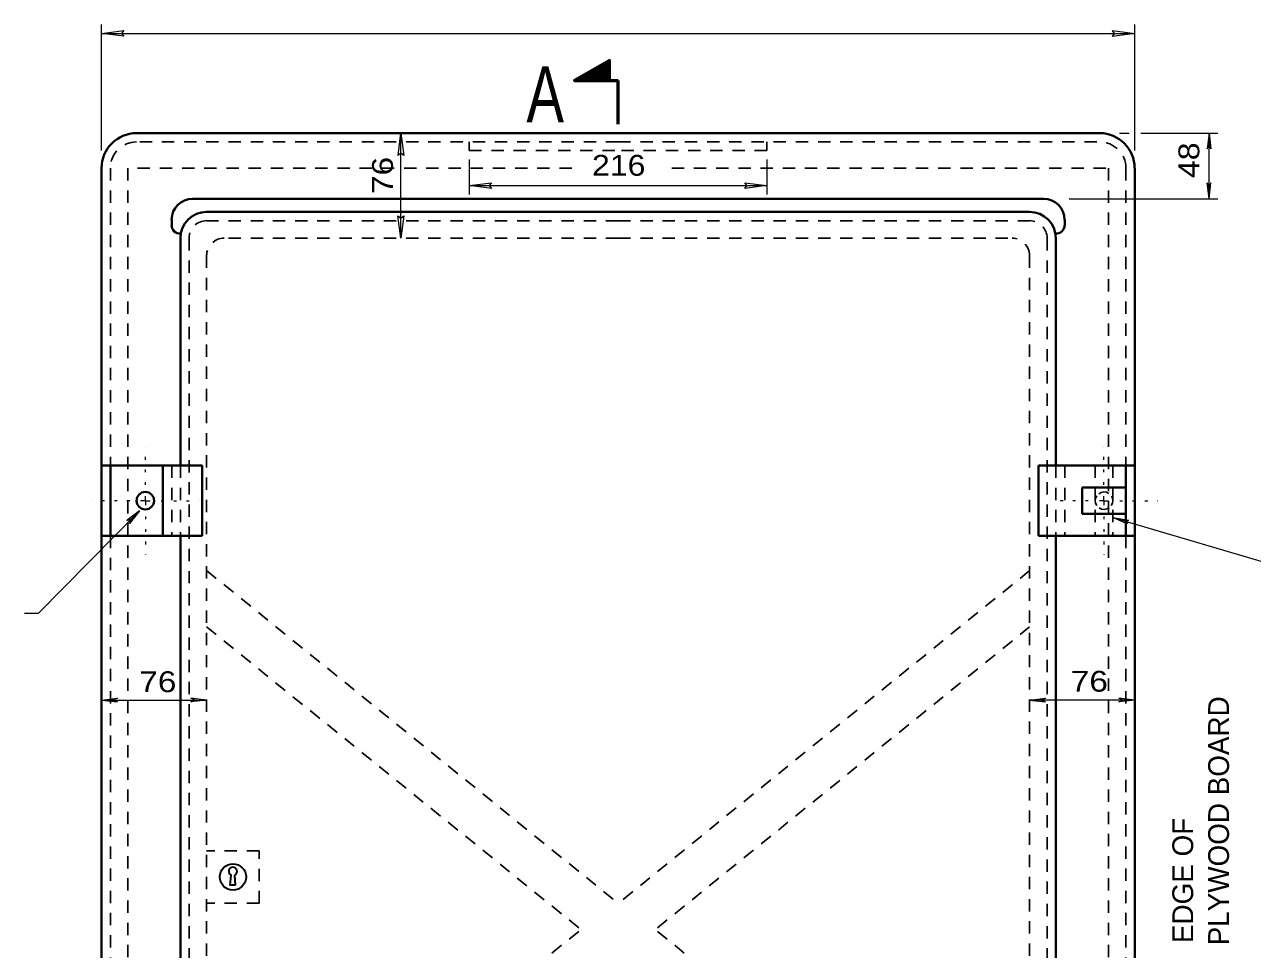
# Model space of a CAD drawing. Extents: x 312583 to 312854, y 144419 to 144597.
# Drawn here: x 312630.5 to 312675.3, y 144489.6 to 144523.37 of the extents above; entities that cross this region are included whole.
import ezdxf
from ezdxf.enums import TextEntityAlignment as Align

# ---------------------------------------------------------------- set-up
doc = ezdxf.new("R2010")
doc.units = 0
doc.header["$LTSCALE"] = 0.3
doc.linetypes.add('DOTTED', pattern=[1.5, 0.3, -1.2])
doc.linetypes.add('SHORT_DASHED', pattern=[2.7, 1.5, -1.2])
doc.layers.add('1', color=7, linetype='Continuous', lineweight=25)
doc.layers.add('2', color=7, linetype='Continuous', lineweight=13)

msp = doc.modelspace()

# ---------------------------------------------------------------- linework, layer by layer
at = {"layer": '1', "lineweight": 40}
for p, q in [((312652.1571, 144519.4027), (312634.5851, 144519.4027)), ((312652.1571, 144519.4027), (312669.7214, 144519.4027)), ((312633.3048, 144518.1223), (312633.3048, 144466.3723)), ((312671.0018, 144518.1223), (312671.0018, 144466.3723)), ((312652.1571, 144517.003), (312636.6321, 144517.003)), ((312652.1571, 144517.003), (312667.6821, 144517.003)), ((312635.8654, 144516.0447), (312635.8654, 144516.2363)), ((312652.1571, 144516.5277), (312637.1381, 144516.5277)), ((312652.1571, 144516.5277), (312667.1684, 144516.5277)), ((312668.4488, 144516.0447), (312668.4488, 144516.2363)), ((312636.1798, 144515.5693), (312636.1798, 144507.2663)), ((312668.1268, 144515.5693), (312668.1268, 144507.2663)), ((312636.9771, 144507.2663), (312633.3048, 144507.2663)), ((312633.6268, 144507.2663), (312633.6268, 144504.7057)), ((312635.5434, 144507.2663), (312635.5434, 144504.7057)), ((312636.9771, 144507.2663), (312636.9771, 144504.7057)), ((312667.4904, 144507.2663), (312671.0018, 144507.2663)), ((312667.4904, 144507.2663), (312667.4904, 144504.7057)), ((312670.6798, 144507.2663), (312670.6798, 144504.7057)), ((312669.0851, 144506.4613), (312669.0851, 144505.503)), ((312669.0851, 144506.4613), (312670.6798, 144506.4613)), ((312669.0851, 144505.503), (312670.6798, 144505.503)), ((312636.9771, 144504.7057), (312633.3048, 144504.7057)), ((312636.1798, 144504.7057), (312636.1798, 144483.6223)), ((312667.4904, 144504.7057), (312671.0018, 144504.7057)), ((312668.1268, 144504.7057), (312668.1268, 144483.6223))]:
    msp.add_line(p, q, dxfattribs=at)
at = {"layer": '1', "linetype": 'SHORT_DASHED'}
for p, q in [((312652.1571, 144519.0807), (312634.5851, 144519.0807)), ((312652.1571, 144519.0807), (312669.7214, 144519.0807)), ((312633.6268, 144518.1223), (312633.6268, 144507.2663)), ((312634.2631, 144518.1223), (312634.2631, 144466.3723)), ((312650.4628, 144518.1223), (312634.2631, 144518.1223)), ((312654.1121, 144518.1223), (312670.0434, 144518.1223)), ((312670.0434, 144518.1223), (312670.0434, 144466.3723)), ((312670.6798, 144518.1223), (312670.6798, 144507.2663)), ((312652.1571, 144516.2057), (312637.1381, 144516.2057)), ((312652.1571, 144516.2057), (312667.1684, 144516.2057)), ((312636.5018, 144515.5693), (312636.5018, 144469.7303)), ((312652.1571, 144515.5693), (312637.7821, 144515.5693)), ((312652.1571, 144515.5693), (312666.5321, 144515.5693)), ((312667.8048, 144515.5693), (312667.8048, 144469.7303)), ((312637.1381, 144514.933), (312637.1381, 144470.3667)), ((312667.1684, 144514.933), (312667.1684, 144470.3667)), ((312635.8654, 144507.2663), (312635.8654, 144504.7057)), ((312636.1798, 144507.2663), (312636.1798, 144504.7057)), ((312668.1268, 144507.2663), (312668.1268, 144504.7057)), ((312668.4488, 144507.2663), (312668.4488, 144504.7057)), ((312669.5604, 144507.2663), (312669.5604, 144504.7057)), ((312670.2044, 144507.2663), (312670.2044, 144504.7057)), ((312633.6268, 144504.7057), (312633.6268, 144483.6223)), ((312670.6798, 144504.7057), (312670.6798, 144483.6223)), ((312637.1381, 144503.433), (312652.1571, 144491.289)), ((312667.1684, 144503.433), (312652.1571, 144491.289)), ((312637.1381, 144501.3783), (312650.8001, 144490.3307)), ((312667.1684, 144501.3783), (312653.5064, 144490.3307)), ((312639.0548, 144493.2057), (312637.1381, 144493.2057)), ((312639.0548, 144491.289), (312639.0548, 144493.2057)), ((312639.0548, 144491.289), (312637.1381, 144491.289)), ((312637.1381, 144479.2907), (312650.8001, 144490.3307)), ((312667.1684, 144479.2907), (312653.5064, 144490.3307))]:
    msp.add_line(p, q, dxfattribs=at)
at = {"layer": '1', "linetype": 'DOTTED', "lineweight": 13}
for p, q in [((312634.9071, 144506.561), (312634.9071, 144507.941)), ((312669.8824, 144506.561), (312669.8824, 144507.941)), ((312634.3321, 144505.986), (312632.9444, 144505.986)), ((312635.4821, 144505.986), (312636.8621, 144505.986)), ((312669.3074, 144505.986), (312667.9274, 144505.986)), ((312670.4574, 144505.986), (312671.8451, 144505.986)), ((312634.9071, 144505.411), (312634.9071, 144504.0233)), ((312669.8824, 144505.411), (312669.8824, 144504.0233))]:
    msp.add_line(p, q, dxfattribs=at)
at = {"layer": '1', "lineweight": 13}
for p, q in [((312634.9071, 144505.986), (312634.7308, 144505.986)), ((312634.9071, 144505.986), (312634.9071, 144506.1547)), ((312634.9071, 144505.986), (312635.0758, 144505.986)), ((312634.9071, 144505.986), (312634.9071, 144505.8173)), ((312669.8824, 144505.986), (312669.7138, 144505.986)), ((312669.8824, 144505.986), (312669.8824, 144506.1547)), ((312669.8824, 144505.986), (312670.0511, 144505.986)), ((312669.8824, 144505.986), (312669.8824, 144505.8173))]:
    msp.add_line(p, q, dxfattribs=at)
at = {"layer": '1', "lineweight": 35}
msp.add_line((312638.1961, 144491.9483), (312638.1654, 144492.3163), dxfattribs=at)
at = {"layer": '1', "linetype": 'SHORT_DASHED'}
for points in [[(312646.7214, 144519.0807), (312646.7214, 144518.7663), (312652.1571, 144518.7663)], [(312657.5851, 144519.0807), (312657.5851, 144518.7663), (312652.1571, 144518.7663)]]:
    msp.add_lwpolyline(points, dxfattribs=at)
at = {"layer": '1', "lineweight": 35}
msp.add_lwpolyline([(312638.1961, 144491.9483), (312637.9968, 144491.9483), (312638.0351, 144492.3163)], dxfattribs=at)
at = {"layer": '1', "lineweight": 40}
msp.add_circle((312634.9033, 144505.986), 0.3194, dxfattribs=at)
at = {"layer": '1', "lineweight": 35}
msp.add_circle((312638.0977, 144492.2499), 0.4792, dxfattribs=at)
at = {"layer": '1', "lineweight": 40}
for centre, radius, start, end in [((312634.5838, 144518.1249), 1.2778, 90, 180), ((312669.7227, 144518.1249), 1.2778, 0, 90), ((312636.6283, 144516.2402), 0.7667, 90, 180), ((312667.6783, 144516.2402), 0.7667, 0, 90), ((312637.1394, 144515.5693), 0.9583, 90, 180), ((312667.1672, 144515.5693), 0.9583, 0, 90), ((312636.181, 144516.0485), 0.3194, 180, 272.41345), ((312668.1255, 144516.0485), 0.3194, 267.58655, 0)]:
    msp.add_arc(centre, radius, start, end, dxfattribs=at)
at = {"layer": '1', "linetype": 'SHORT_DASHED'}
for centre, radius, start, end in [((312634.5838, 144518.1249), 0.9583, 90, 180), ((312669.7227, 144518.1249), 0.9583, 0, 90), ((312637.1394, 144515.5693), 0.6389, 90, 180), ((312667.1672, 144515.5693), 0.6389, 0, 90), ((312637.7783, 144514.9304), 0.6389, 90, 180), ((312666.5283, 144514.9304), 0.6389, 0, 90)]:
    msp.add_arc(centre, radius, start, end, dxfattribs=at)
at = {"layer": '1'}
for start, end in [(56.61149, 126.70759), (145.14079, 213.35403), (326.83677, 32.29727), (236.53462, 306.15074)]:
    msp.add_arc((312669.8824, 144505.986), 0.3194, start, end, dxfattribs=at)
at = {"layer": '1', "lineweight": 35}
msp.add_arc((312638.0964, 144492.4556), 0.1521, 295.8624, 245.15761, dxfattribs=at)
at = {"layer": '2'}
for p, q in [((312633.3048, 144518.7663), (312633.3048, 144523.3663)), ((312671.0018, 144518.7663), (312671.0018, 144523.3663)), ((312633.3048, 144523.0443), (312671.0018, 144523.0443)), ((312644.2298, 144515.5693), (312644.2298, 144519.4027)), ((312670.4421, 144519.4027), (312670.8024, 144519.4027)), ((312671.2241, 144519.4027), (312674.0378, 144519.4027)), ((312673.7158, 144519.4027), (312673.6468, 144518.8277)), ((312673.7158, 144517.003), (312673.7158, 144519.4027)), ((312673.7158, 144519.4027), (312673.7848, 144518.8277)), ((312673.6468, 144518.8277), (312673.7158, 144519.0117)), ((312673.7848, 144518.8277), (312673.7158, 144519.0117)), ((312646.7214, 144518.4443), (312646.7214, 144517.164)), ((312657.5851, 144518.4443), (312657.5851, 144517.164)), ((312646.7214, 144517.486), (312657.5851, 144517.486)), ((312673.6468, 144517.5857), (312673.7158, 144517.4017)), ((312673.7158, 144517.003), (312673.6468, 144517.5857)), ((312673.7848, 144517.5857), (312673.7158, 144517.4017)), ((312673.7158, 144517.003), (312673.7848, 144517.5857)), ((312668.6174, 144517.003), (312674.0378, 144517.003)), ((312631.0048, 144501.8767), (312634.6848, 144505.618)), ((312634.6848, 144505.618), (312634.2248, 144505.2577)), ((312634.6848, 144505.618), (312634.3244, 144505.158)), ((312634.2248, 144505.2577), (312634.4088, 144505.3343)), ((312634.3244, 144505.158), (312634.4088, 144505.3343)), ((312630.4957, 144501.8767), (312631.0048, 144501.8767)), ((312633.3048, 144498.7103), (312633.8874, 144498.7793)), ((312633.3048, 144498.7103), (312637.1381, 144498.7103)), ((312633.3048, 144498.7103), (312633.8874, 144498.6413)), ((312633.8874, 144498.7793), (312633.7034, 144498.7103)), ((312633.8874, 144498.6413), (312633.7034, 144498.7103)), ((312636.5631, 144498.7793), (312636.7471, 144498.7103)), ((312637.1381, 144498.7103), (312636.5631, 144498.7793)), ((312636.5631, 144498.6413), (312636.7471, 144498.7103)), ((312637.1381, 144498.7103), (312636.5631, 144498.6413)), ((312667.1684, 144498.7103), (312667.7434, 144498.7793)), ((312671.0018, 144498.7103), (312667.1684, 144498.7103)), ((312667.1684, 144498.7103), (312667.7434, 144498.6413)), ((312667.7434, 144498.7793), (312667.5594, 144498.7103)), ((312667.7434, 144498.6413), (312667.5594, 144498.7103)), ((312670.4268, 144498.7793), (312670.6108, 144498.7103)), ((312671.0018, 144498.7103), (312670.4268, 144498.7793)), ((312670.4268, 144498.6413), (312670.6108, 144498.7103)), ((312671.0018, 144498.7103), (312670.4268, 144498.6413))]:
    msp.add_line(p, q, dxfattribs=at)
at = {"layer": '2', "lineweight": 35}
for p, q in [((312651.8351, 144521.6183), (312651.6511, 144521.948)), ((312651.8351, 144521.6567), (312651.6588, 144521.9557)), ((312651.8351, 144521.6873), (312651.6741, 144521.9633)), ((312651.8351, 144521.718), (312651.6894, 144521.971)), ((312651.8351, 144521.7487), (312651.6971, 144521.9787)), ((312651.8351, 144521.7793), (312651.7201, 144521.9863)), ((312651.8351, 144521.81), (312651.7278, 144521.994)), ((312651.8351, 144521.8407), (312651.7431, 144522.0017)), ((312651.8351, 144521.879), (312651.7584, 144522.0093)), ((312651.8351, 144521.902), (312651.7738, 144522.017)), ((312651.8351, 144521.9403), (312651.7891, 144522.0247)), ((312651.8351, 144521.971), (312651.8044, 144522.0323)), ((312651.8351, 144522.0093), (312651.8121, 144522.04)), ((312651.8351, 144522.04), (312651.8274, 144522.0477)), ((312650.9764, 144521.3193), (312650.8768, 144521.5033)), ((312650.9918, 144521.3193), (312650.8844, 144521.5033)), ((312651.0148, 144521.3193), (312650.8998, 144521.5187)), ((312651.0378, 144521.3193), (312650.9151, 144521.5187)), ((312651.0531, 144521.3193), (312650.9304, 144521.534)), ((312651.0684, 144521.3193), (312650.9458, 144521.534)), ((312651.0838, 144521.3193), (312650.9611, 144521.5493)), ((312651.1068, 144521.3193), (312650.9688, 144521.557)), ((312651.1221, 144521.3193), (312650.9841, 144521.5647)), ((312651.1451, 144521.3193), (312650.9994, 144521.5723)), ((312651.1604, 144521.3193), (312651.0071, 144521.58)), ((312651.1834, 144521.3193), (312651.0224, 144521.5877)), ((312651.1988, 144521.3193), (312651.0378, 144521.5953)), ((312651.2141, 144521.3193), (312651.0531, 144521.603)), ((312651.2371, 144521.3193), (312651.0684, 144521.6107)), ((312651.2524, 144521.3193), (312651.0838, 144521.6183)), ((312651.2678, 144521.3193), (312651.0991, 144521.626)), ((312651.2908, 144521.3193), (312651.1068, 144521.6337)), ((312651.3138, 144521.3193), (312651.1221, 144521.6413)), ((312651.3291, 144521.3193), (312651.1374, 144521.649)), ((312651.3444, 144521.3193), (312651.1451, 144521.6567)), ((312651.3674, 144521.3193), (312651.1604, 144521.6643)), ((312651.3828, 144521.3193), (312651.1758, 144521.672)), ((312651.4058, 144521.3193), (312651.1911, 144521.6873)), ((312651.4211, 144521.3193), (312651.2064, 144521.6873)), ((312651.4364, 144521.3193), (312651.2218, 144521.7027)), ((312651.4518, 144521.3193), (312651.2371, 144521.7027)), ((312651.4748, 144521.3193), (312651.2524, 144521.718)), ((312651.4978, 144521.3193), (312651.2601, 144521.718)), ((312651.5131, 144521.3193), (312651.2754, 144521.7333)), ((312651.5284, 144521.3193), (312651.2908, 144521.7333)), ((312651.5438, 144521.3193), (312651.2984, 144521.7487)), ((312651.5668, 144521.3193), (312651.3138, 144521.7487)), ((312651.5898, 144521.3193), (312651.3291, 144521.764)), ((312651.6051, 144521.3193), (312651.3444, 144521.764)), ((312651.6204, 144521.3193), (312651.3598, 144521.7793)), ((312651.6434, 144521.3193), (312651.3751, 144521.787)), ((312651.6588, 144521.3193), (312651.3904, 144521.7947)), ((312651.6818, 144521.3193), (312651.3981, 144521.8023)), ((312651.6971, 144521.3193), (312651.4134, 144521.81)), ((312651.7124, 144521.3193), (312651.4288, 144521.8177)), ((312651.7354, 144521.3193), (312651.4364, 144521.8253)), ((312651.7508, 144521.3193), (312651.4518, 144521.833)), ((312651.7738, 144521.3193), (312651.4671, 144521.8407)), ((312651.7891, 144521.3193), (312651.4824, 144521.8483)), ((312651.8044, 144521.3193), (312651.4978, 144521.856)), ((312651.8274, 144521.3193), (312651.5131, 144521.8637)), ((312651.8351, 144521.3347), (312651.5208, 144521.8713)), ((312651.8351, 144521.3653), (312651.5438, 144521.879)), ((312651.8351, 144521.396), (312651.5514, 144521.8867)), ((312651.8351, 144521.4267), (312651.5668, 144521.8943)), ((312651.8351, 144521.4573), (312651.5821, 144521.902)), ((312651.8351, 144521.488), (312651.5898, 144521.9173)), ((312651.8351, 144521.5187), (312651.6051, 144521.9173)), ((312651.8351, 144521.557), (312651.6204, 144521.9327)), ((312651.8351, 144521.5877), (312651.6358, 144521.9403)), ((312650.5701, 144521.3193), (312650.5701, 144521.327)), ((312650.5931, 144521.3193), (312650.5854, 144521.3347)), ((312650.6084, 144521.3193), (312650.5931, 144521.3423)), ((312650.6238, 144521.3193), (312650.6084, 144521.35)), ((312650.6468, 144521.3193), (312650.6238, 144521.3577)), ((312650.6621, 144521.3193), (312650.6391, 144521.3653)), ((312650.6851, 144521.3193), (312650.6544, 144521.373)), ((312650.7004, 144521.3193), (312650.6698, 144521.3807)), ((312650.7234, 144521.3193), (312650.6774, 144521.3883)), ((312650.7388, 144521.3193), (312650.6928, 144521.396)), ((312650.7541, 144521.3193), (312650.7081, 144521.4037)), ((312650.7771, 144521.3193), (312650.7234, 144521.4113)), ((312650.7924, 144521.3193), (312650.7311, 144521.419)), ((312650.8078, 144521.3193), (312650.7464, 144521.4267)), ((312650.8308, 144521.3193), (312650.7618, 144521.4343)), ((312650.8538, 144521.3193), (312650.7771, 144521.442)), ((312650.8691, 144521.3193), (312650.7924, 144521.4573)), ((312650.8844, 144521.3193), (312650.8078, 144521.4573)), ((312650.8998, 144521.3193), (312650.8154, 144521.4727)), ((312650.9228, 144521.3193), (312650.8308, 144521.4727)), ((312650.9458, 144521.3193), (312650.8461, 144521.488)), ((312650.9611, 144521.3193), (312650.8538, 144521.488))]:
    msp.add_line(p, q, dxfattribs=at)
at = {"layer": '2', "lineweight": 53}
for p in [(312651.8351, 144521.3193), (312652.1571, 144519.7247)]:
    msp.add_line(p, (312652.1571, 144521.3193), dxfattribs=at)
at = {"layer": '2'}
for points in [[(312634.1181, 144522.9449), (312633.3048, 144523.0443), (312634.1181, 144523.1527), (312634.0367, 144523.0443)], [(312670.1885, 144523.1437), (312671.0018, 144523.0443), (312670.1885, 144522.9359), (312670.2699, 144523.0443)], [(312644.1304, 144518.5894), (312644.2298, 144519.4027), (312644.3382, 144518.5894), (312644.2298, 144518.6708)], [(312647.5347, 144517.3866), (312646.7214, 144517.486), (312647.5347, 144517.5944), (312647.4533, 144517.486)], [(312656.7718, 144517.5854), (312657.5851, 144517.486), (312656.7718, 144517.3776), (312656.8532, 144517.486)], [(312644.3292, 144516.3826), (312644.2298, 144515.5693), (312644.1214, 144516.3826), (312644.2298, 144516.3012)], [(312670.7334, 144505.1427), (312670.2044, 144505.3727), (312670.7794, 144505.2807), (312670.6951, 144505.227)]]:
    msp.add_lwpolyline(points, close=True, dxfattribs=at)
at = {"layer": '2', "lineweight": 53}
msp.add_lwpolyline([(312651.8351, 144521.3193), (312651.8351, 144522.0553), (312650.5624, 144521.3193)], close=True, dxfattribs=at)
at = {"layer": '2'}
msp.add_lwpolyline([(312670.2044, 144505.3727), (312676.6368, 144503.4713), (312683.0844, 144505.434)], dxfattribs=at)

# ---------------------------------------------------------------- texts
for s, height, width, p in [('A', 2.044, 0.75, (312649.4929, 144519.8013)), ('216 ', 0.76, 1.15, (312652.3369, 144517.8483)), ('76 ', 0.76, 1.2, (312635.5281, 144498.9982)), ('76 ', 0.76, 1.2, (312669.5169, 144499.0141))]:
    msp.add_text(s, height=height, dxfattribs=dict(at, width=width)).set_placement(p, align=Align.CENTER)
for s, width, p in [('48 ', 1.15, (312673.3591, 144518.5742)), ('76 ', 1.2, (312643.9365, 144518.0262))]:
    msp.add_text(s, height=0.76, rotation=90, dxfattribs=dict(at, width=width)).set_placement(p, align=Align.CENTER)
for s, p in [('PLYWOOD BOARD', (312674.4433, 144494.2998)), ('EDGE OF', (312673.1355, 144492.1248))]:
    msp.add_text(s, height=0.76, rotation=90, dxfattribs=at).set_placement(p, align=Align.CENTER)

doc.saveas('drawing.dxf')
